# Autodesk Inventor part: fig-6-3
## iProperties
Created: 2004-05
Part Number: fig-6-3
Document SubType Name: Modeling
Designer: CADCIM Technologies
Manufacturer: Standard
Standards Organization: Custom
Density: 1 g/cm^3
Author: CADCIM Technologies
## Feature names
1. Extrusion1
2. Hole1
3. Circular Pattern1
